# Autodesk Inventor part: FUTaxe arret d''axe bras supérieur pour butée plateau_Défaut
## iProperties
Shininess: 64.0
Length Units: 11269
Angle Units: 11279
Time Units: 11290
Mass Units: 11283
Length Display Precision: 3
Angle Display Precision: 2
Compacted: True
Part Number: FUTaxe arret d''axe bras supérieur pour butée plateau_Défaut
Document SubType Name: Modeling
Created: 2006-11
Material: Par défaut
Designer: profs_sti
Density: 0.0
Volumn: 0.0
Area: 0.0
PropertySet Name: Model Information
Control State: 0
Master: False
Checked Out: False
Author: profs_sti
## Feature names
1. Base1
